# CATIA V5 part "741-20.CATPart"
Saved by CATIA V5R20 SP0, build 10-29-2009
Part number: 741-20
Bounding box of the stored display mesh (mm): x -20 to 19.743, y -19.969 to 19.925, z -23 to 20
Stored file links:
  C:\Users\Utente\Desktop\IO LAVORO\3D X SITO CF\X SITO\741\741-20.CATPart
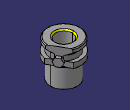
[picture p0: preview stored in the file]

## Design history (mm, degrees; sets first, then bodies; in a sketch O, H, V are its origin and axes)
Set1
  DatumSurface1 to DatumSurface42 "741-20"
Body1 (main body)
